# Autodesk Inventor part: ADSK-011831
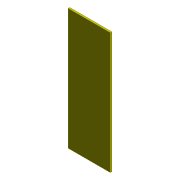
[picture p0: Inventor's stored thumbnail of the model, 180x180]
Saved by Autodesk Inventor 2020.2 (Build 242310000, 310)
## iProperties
Created: 1999-11
Part Number: ADSK-011831
Document SubType Name: Modeling
Designer: sspink
Material: Générique
Density: 1 g/cm^3
Appearance: Gelb
Mass: 50.9355 g
Surface Area: 357.42 cm^2
Volume: 50.9355 cm^3
Control State: 0
Checked Out: False
Last Check In By: sspink
Last Check In Date: 1999-12-22
Master: False
Shininess: 0.0
Length Units: 11269
Angle Units: 11279
Time Units: 11290
Mass Units: 11283
Length Display Precision: 3
Angle Display Precision: 2
Compacted: True
Dimensions: 220,5x3x77 mm
Mass: 0,051 kg
VLT_Material: Generisch
Density: 0.0
Volumn: 0.0
Area: 0.0
PropertySet Name: Model Information
Author: sspink
Revision Number: -
Title: ADSK-011831
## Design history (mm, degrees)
node "Solide1"
  node "Extrusion1" dims "d2" = 3, "d3" = 0
sketch "Sketch1"
  geometry: L1 (59.865, 114.43)-(59.865, -106.07) reference; L2 (59.865, -106.07)-(136.865, -106.07) reference; L3 (136.865, -106.07)-(136.865, 114.43); L4 (136.865, 114.43)-(59.865, 114.43)
  constraints: 8 end point, 2 parallel, 2 vertical, 1 horizontal, 1 perpendicular
  dimensions: "d0" = 220.5 distance of L2.end L3.end; "d1" = 77 distance of L1.end L2.end
node "Corps solides"
node "Corps surfaciques"
